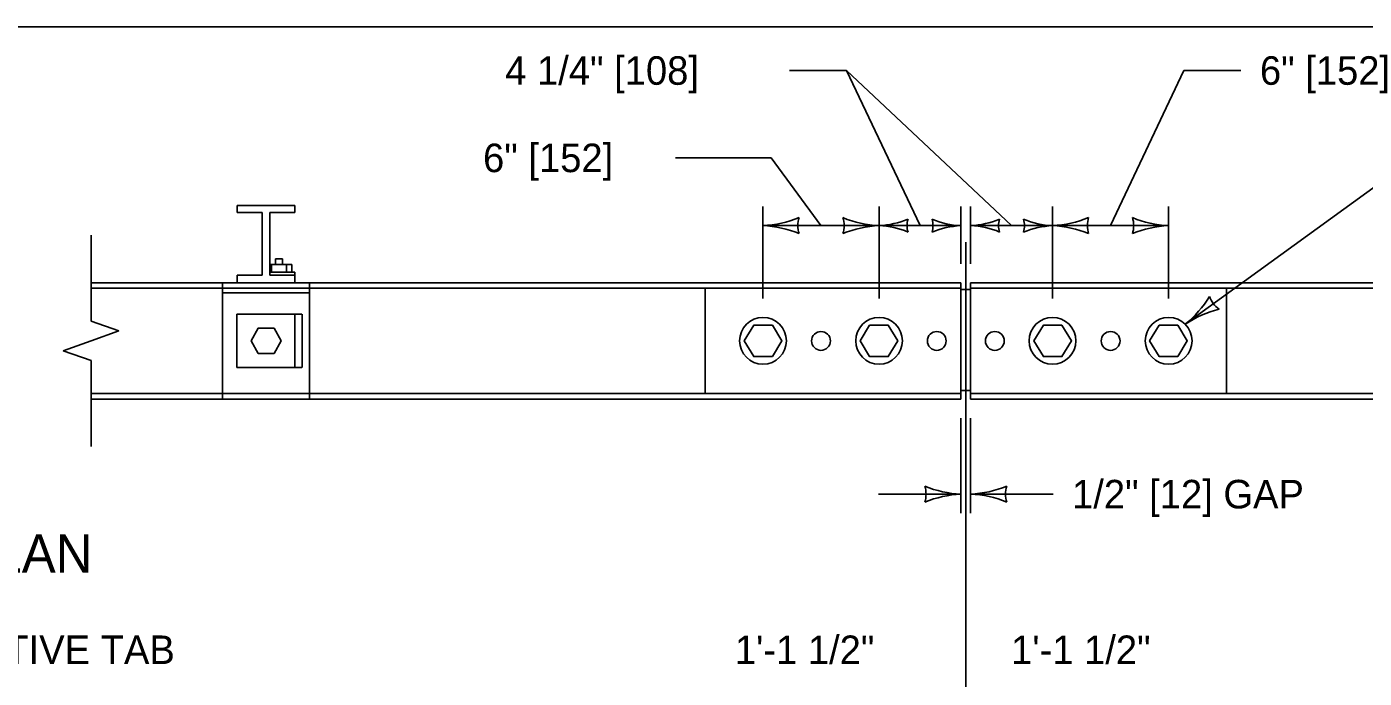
# Model space of a CAD drawing. Extents: x 49991.4 to 50021, y 49987.6 to 50011.4.
# Drawn here: x 50015.133 to 50017.948, y 50006.795 to 50008.165 of the extents above; entities that cross this region are included whole.
import ezdxf

# ---------------------------------------------------------------- set-up
doc = ezdxf.new("R2010")
doc.units = 0
for name, color, linetype in [('Level 1', 7, 'Continuous'), ('Level 2', 7, 'Continuous'), ('Level 3', 7, 'Continuous'), ('Level 4', 7, 'Continuous'), ('Level 5', 7, 'Continuous'), ('Level 6', 7, 'Continuous')]:
    doc.layers.add(name, color=color, linetype=linetype)

msp = doc.modelspace()

# ---------------------------------------------------------------- linework, layer by layer
at = {"layer": 'Level 1'}
for p, q in [((50015.5757, 50007.7742), (50015.5757, 50007.7888)), ((50015.5757, 50007.7888), (50015.6975, 50007.7888)), ((50015.5757, 50007.7742), (50015.6286, 50007.7742)), ((50015.6286, 50007.6422), (50015.6286, 50007.7742)), ((50015.6445, 50007.6422), (50015.6445, 50007.7742)), ((50015.6445, 50007.7742), (50015.6975, 50007.7742)), ((50015.6975, 50007.7742), (50015.6975, 50007.7888)), ((50015.6445, 50007.6649), (50015.6908, 50007.6649)), ((50015.6484, 50007.6485), (50015.6484, 50007.6649)), ((50015.6799, 50007.6485), (50015.6799, 50007.6649)), ((50015.6908, 50007.6485), (50015.6908, 50007.6649)), ((50015.5757, 50007.6422), (50015.6286, 50007.6422)), ((50015.5757, 50007.6264), (50015.5757, 50007.6422)), ((50015.6445, 50007.6485), (50015.6972, 50007.6485)), ((50015.6445, 50007.6422), (50015.6975, 50007.6422)), ((50015.6972, 50007.6422), (50015.6972, 50007.6485)), ((50015.6975, 50007.6264), (50015.6975, 50007.6422)), ((50017.0989, 50007.6264), (50015.2686, 50007.6264)), ((50017.0989, 50007.3818), (50017.0989, 50007.6264)), ((50017.0989, 50007.6118), (50017.1193, 50007.6118)), ((50017.1193, 50007.3818), (50017.1193, 50007.6264)), ((50019.3683, 50007.6264), (50017.1193, 50007.6264)), ((50015.5752, 50007.5601), (50015.7122, 50007.5601)), ((50015.5754, 50007.4479), (50015.5754, 50007.5601)), ((50015.6973, 50007.4479), (50015.6973, 50007.5601)), ((50015.7125, 50007.4479), (50015.7125, 50007.5601)), ((50016.9066, 50007.4711), (50016.9458, 50007.4711)), ((50017.3114, 50007.4711), (50017.2723, 50007.4711)), ((50015.5752, 50007.4479), (50015.7122, 50007.4479)), ((50017.0989, 50007.3818), (50015.2686, 50007.3818)), ((50017.0989, 50007.3996), (50017.1193, 50007.3996)), ((50019.3683, 50007.3818), (50017.1193, 50007.3818))]:
    msp.add_line(p, q, dxfattribs=at)
for points in [[(50020.9378, 50008.1646), (50009.7374, 50008.1646), (50009.7374, 49999.8856), (50020.9378, 49999.8856)], [(50015.6202, 50007.4777), (50015.6536, 50007.4777), (50015.6683, 50007.5044), (50015.6536, 50007.5311), (50015.6202, 50007.5311), (50015.6055, 50007.5044)], [(50016.7021, 50007.5371), (50016.7223, 50007.5041), (50016.7021, 50007.4711), (50016.663, 50007.4711), (50016.6429, 50007.5041), (50016.663, 50007.5371)], [(50016.9066, 50007.5371), (50016.8865, 50007.5041), (50016.9066, 50007.4711), (50016.9458, 50007.4711), (50016.966, 50007.5041), (50016.9458, 50007.5371)], [(50017.3114, 50007.5371), (50017.3316, 50007.5041), (50017.3114, 50007.4711), (50017.2723, 50007.4711), (50017.2522, 50007.5041), (50017.2723, 50007.5371)], [(50017.516, 50007.5371), (50017.4958, 50007.5041), (50017.516, 50007.4711), (50017.555, 50007.4711), (50017.5752, 50007.5041), (50017.555, 50007.5371)]]:
    msp.add_lwpolyline(points, close=True, dxfattribs=at)
for points in [[(50015.6568, 50007.6649), (50015.6568, 50007.6767)], [(50015.6568, 50007.6767), (50015.671, 50007.6767)], [(50015.671, 50007.6649), (50015.671, 50007.6767)]]:
    msp.add_lwpolyline(points, dxfattribs=at)
for centre in [(50016.6823, 50007.5043), (50016.9266, 50007.5043), (50017.2916, 50007.5043), (50017.5359, 50007.5043)]:
    msp.add_circle(centre, 0.0492, dxfattribs=at)
at = {"layer": 'Level 3'}
for p, q in [((50016.8581, 50008.0726), (50016.7383, 50008.0726)), ((50017.2054, 50007.7464), (50016.8581, 50008.0726)), ((50016.8581, 50008.0726), (50017.0128, 50007.7464)), ((50017.5682, 50008.0726), (50017.4136, 50007.7464)), ((50017.5682, 50008.0726), (50017.688, 50008.0726)), ((50016.6993, 50007.8889), (50016.4983, 50007.8889)), ((50016.8044, 50007.7464), (50016.6993, 50007.8889)), ((50016.9266, 50007.7864), (50016.9266, 50007.5935)), ((50017.2915, 50007.7464), (50017.2915, 50007.7864)), ((50016.9266, 50007.7464), (50017.0989, 50007.7464)), ((50017.2915, 50007.7464), (50017.1192, 50007.7464)), ((50017.2915, 50007.7464), (50017.2916, 50007.5935))]:
    msp.add_line(p, q, dxfattribs=at)
for points in [[(50017.5707, 50007.5391), (50018.3072, 50008.0726)], [(50016.6823, 50007.5935), (50016.6822, 50007.7864)], [(50017.0989, 50007.6664), (50017.0989, 50007.7864)], [(50017.0989, 50007.6664), (50017.0989, 50007.7784)], [(50017.1193, 50007.6664), (50017.1193, 50007.7864)], [(50017.1193, 50007.6664), (50017.1193, 50007.7784)], [(50017.5358, 50007.5935), (50017.5358, 50007.7864)], [(50016.6822, 50007.7464), (50016.9266, 50007.7464)], [(50017.5358, 50007.7464), (50017.2915, 50007.7464)], [(50017.0989, 50007.3418), (50017.0989, 50007.1418)], [(50017.1193, 50007.3418), (50017.1193, 50007.1418)], [(50016.9255, 50007.1818), (50017.0989, 50007.1818)], [(50017.1193, 50007.1818), (50017.2927, 50007.1818)]]:
    msp.add_lwpolyline(points, dxfattribs=at)
for centre, radius, start, end in [((50016.6707, 50007.9791), 0.233, 272.8273, 292.0772), ((50016.6731, 50007.5243), 0.2223, 67.456, 87.6395), ((50016.8104, 50007.7464), 0.0548, 162.1388, 197.8612), ((50016.9358, 50007.9685), 0.2223, 247.456, 267.6395), ((50016.7984, 50007.7464), 0.0548, 342.1388, 17.8612), ((50016.9381, 50007.5137), 0.233, 92.8273, 112.0772), ((50016.9174, 50007.9326), 0.1864, 272.8273, 292.0772), ((50016.9193, 50007.5687), 0.1779, 67.456, 87.6395), ((50017.0292, 50007.7464), 0.0438, 162.1388, 197.8612), ((50017.1062, 50007.9241), 0.1779, 247.456, 267.6395), ((50016.9963, 50007.7464), 0.0438, 342.1388, 17.8612), ((50017.1081, 50007.5602), 0.1864, 92.8273, 112.0772), ((50017.1101, 50007.9326), 0.1864, 272.8273, 292.0772), ((50017.112, 50007.5687), 0.1779, 67.456, 87.6395), ((50017.2219, 50007.7464), 0.0438, 162.1388, 197.8612), ((50017.2988, 50007.9241), 0.1779, 247.456, 267.6395), ((50017.1889, 50007.7464), 0.0438, 342.1388, 17.8612), ((50017.3007, 50007.5602), 0.1864, 92.8273, 112.0772), ((50017.28, 50007.9791), 0.233, 272.8273, 292.0772), ((50017.2824, 50007.5243), 0.2223, 67.456, 87.6395), ((50017.4197, 50007.7464), 0.0548, 162.1388, 197.8612), ((50017.5449, 50007.9685), 0.2223, 247.456, 267.6395), ((50017.4076, 50007.7464), 0.0548, 342.1388, 17.8612), ((50017.5473, 50007.5137), 0.233, 92.8273, 112.0772), ((50017.4237, 50007.7199), 0.233, 309.1182, 328.3681), ((50017.674, 50007.615), 0.0548, 198.4297, 234.1521), ((50017.6948, 50007.3546), 0.2223, 103.7469, 123.9304), ((50017.1081, 50007.4039), 0.2223, 247.456, 267.6395), ((50016.9707, 50007.1818), 0.0548, 342.1388, 17.8612), ((50017.1078, 50007.4145), 0.233, 272.8273, 292.0772), ((50017.2475, 50007.1818), 0.0548, 162.1388, 197.8612), ((50017.1104, 50006.9491), 0.233, 92.8273, 112.0772), ((50017.1101, 50006.9597), 0.2223, 67.456, 87.6395)]:
    msp.add_arc(centre, radius, start, end, dxfattribs=at)
at = {"layer": 'Level 4'}
for p, q in [((50017.0989, 50007.615), (50015.2686, 50007.615)), ((50015.545, 50007.3818), (50015.545, 50007.6264)), ((50015.545, 50007.6053), (50015.7278, 50007.6053)), ((50015.7278, 50007.3818), (50015.7278, 50007.6264)), ((50016.5607, 50007.3932), (50016.5607, 50007.615)), ((50019.3683, 50007.615), (50017.1193, 50007.615)), ((50017.6574, 50007.3932), (50017.6574, 50007.615)), ((50017.0989, 50007.3932), (50015.2686, 50007.3932)), ((50019.3683, 50007.3932), (50017.1193, 50007.3932))]:
    msp.add_line(p, q, dxfattribs=at)
for centre in [(50016.8044, 50007.504), (50017.048, 50007.504), (50017.1702, 50007.504), (50017.4138, 50007.504)]:
    msp.add_circle(centre, 0.0198, dxfattribs=at)
at = {"layer": 'Level 5'}
msp.add_lwpolyline([(50017.109, 50007.7118), (50017.109, 50006.1981)], dxfattribs=at)
at = {"layer": 'Level 6'}
for p, q in [((50015.2686, 50007.7264), (50015.2686, 50007.5456)), ((50015.327, 50007.5249), (50015.2686, 50007.5456)), ((50015.327, 50007.5249), (50015.2686, 50007.5042)), ((50015.2686, 50007.5042), (50015.2101, 50007.4834)), ((50015.2686, 50007.4627), (50015.2101, 50007.4834)), ((50015.2686, 50007.4627), (50015.2686, 50007.2818))]:
    msp.add_line(p, q, dxfattribs=at)

# ---------------------------------------------------------------- texts
at = {"layer": 'Level 2'}
for s, height, p in [('4 1/4" [108]', 0.06, (50016.1399, 50008.0426)), ('6" [152]', 0.06, (50016.0933, 50007.8589)), ('1/2" [12] GAP', 0.06, (50017.3327, 50007.1518)), ('PLAN', 0.08, (50014.9918, 50007.017)), ('REFLECTIVE TAB', 0.06, (50014.7715, 50006.8246)), ('1\'-1 1/2"', 0.06, (50016.6232, 50006.8245)), ('1\'-1 1/2"', 0.06, (50017.2044, 50006.8245))]:
    msp.add_text(s, height=height, dxfattribs=at).set_placement(p)
msp.add_text('6" [152]', height=0.06, rotation=360, dxfattribs=at).set_placement((50017.728, 50008.0426))

doc.saveas('drawing.dxf')
